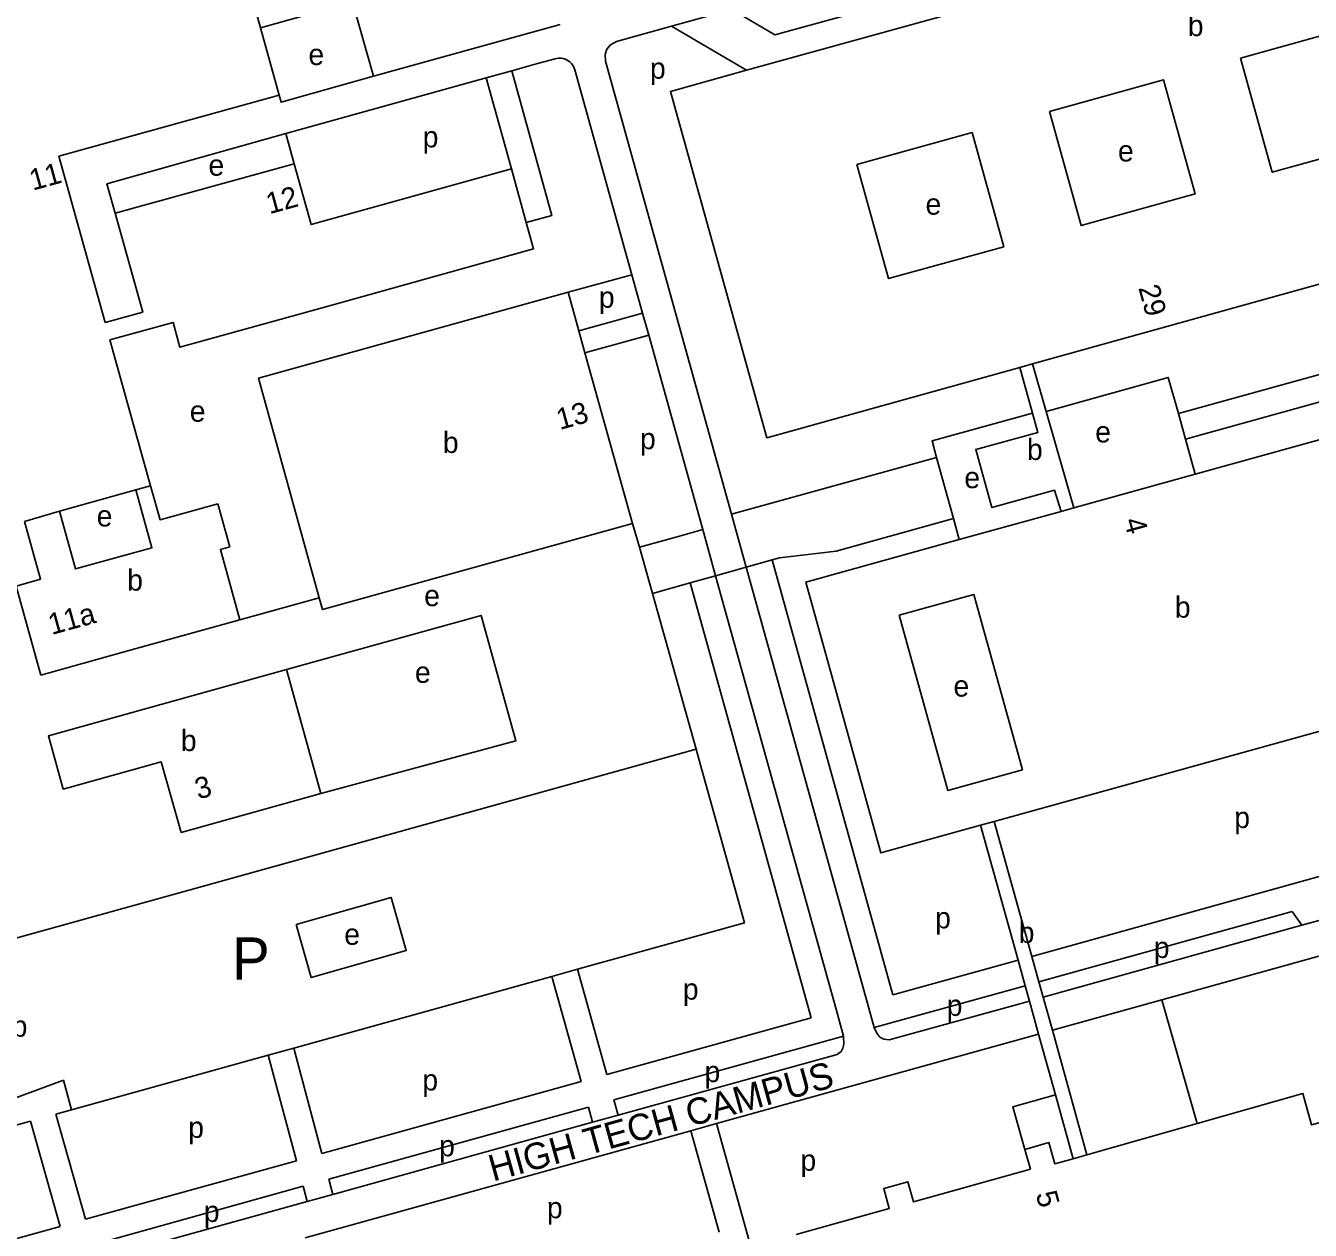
# Model space of a CAD drawing. Extents: x 158358 to 160383, y 379531 to 380764.
# Drawn here: x 159510.8 to 159753.6, y 380106.3 to 380334.2 of the extents above; entities that cross this region are included whole.
import ezdxf

# ---------------------------------------------------------------- set-up
doc = ezdxf.new("R2010")
doc.units = 0
for name, color, linetype in [('BLT_Basislijn', 7, 'Continuous'), ('BLT_Bebouwing', 7, 'Continuous'), ('BLT_Centroide', 7, 'Continuous'), ('BLT_Huisnummer', 7, 'Continuous'), ('BLT_Huisnummer_reeks', 7, 'Continuous'), ('BLT_Onderverdeling_panden', 7, 'Continuous'), ('BLT_Straatnaam', 7, 'Continuous'), ('BLT_Tekst_parkeren', 7, 'Continuous'), ('BLT_Vlakafsluiter', 7, 'Continuous')]:
    doc.layers.add(name, color=color, linetype=linetype)

msp = doc.modelspace()

# ---------------------------------------------------------------- linework, layer by layer
at = {"layer": 'BLT_Basislijn'}
for p, q in [((159647.01, 380325.72), (159632.85, 380334.04)), ((159602.59, 380307.08), (159597.81, 380324.29)), ((159613.28, 380283.77), (159625.32, 380287.07)), ((159627.35, 380279.77), (159625.32, 380287.07)), ((159615.3, 380276.47), (159627.35, 380279.77)), ((159628.51, 380275.61), (159627.35, 380279.77)), ((159616.46, 380272.31), (159628.51, 380275.61)), ((159638.72, 380238.86), (159628.51, 380275.61)), ((159682.93, 380252.51), (159686.12, 380240.96)), ((159626.8, 380235.51), (159625.42, 380240.04)), ((159638.72, 380238.86), (159633.91, 380237.51)), ((159633.91, 380237.51), (159626.8, 380235.51)), ((159636.34, 380228.77), (159629.24, 380226.78)), ((159641.15, 380230.12), (159636.34, 380228.77)), ((159566.23, 380225.94), (159551.25, 380221.82)), ((159700.92, 380158.15), (159776.17, 380179.06)), ((159702.26, 380153.33), (159750.14, 380166.64)), ((159750.14, 380166.64), (159751.98, 380164.03)), ((159620.59, 380135.81), (159615.03, 380155.71)), ((159674.68, 380150.85), (159698.32, 380157.42)), ((159615.77, 380134.47), (159610.21, 380154.37)), ((159671.13, 380144.67), (159699.65, 380152.6)), ((159664.01, 380147.89), (159665.35, 380143.07)), ((159671.13, 380144.67), (159669.79, 380149.49)), ((159725.52, 380149.93), (159732.18, 380126.53)), ((159566.75, 380120.85), (159561.41, 380140.81)), ((159561.93, 380119.51), (159556.59, 380139.48)), ((159622.74, 380128.11), (159621.93, 380131)), ((159617.92, 380126.77), (159617.11, 380129.66)), ((159517.25, 380107.09), (159511.64, 380126.98)), ((159522.06, 380108.43), (159516.45, 380128.32)), ((159641.3, 380126.52), (159647.79, 380103.2)), ((159636.48, 380125.18), (159641.83, 380105.97)), ((159563.99, 380111.78), (159563.22, 380114.68)), ((159568.81, 380113.12), (159568.04, 380116.02))]:
    msp.add_line(p, q, dxfattribs=at)
for points in [[(159644.21, 380337.2), (159652.38, 380332.4), (159681.59, 380340.51), (159679.69, 380347.06)], [(159555.14, 380333.77), (159572.55, 380338.64), (159576.49, 380324.6)], [(159632.85, 380334.04), (159644.21, 380337.2)], [(159576.49, 380324.6), (159611.78, 380334.41)], [(159644.14, 380241.8), (159620.33, 380327.45), (159620.27, 380328.69), (159620.61, 380329.72), (159621.29, 380330.54), (159622.42, 380331.14), (159632.85, 380334.04)], [(159625.32, 380287.07), (159614.55, 380325.84), (159614.3, 380326.45), (159613.96, 380326.96), (159613.6, 380327.33), (159613.13, 380327.65), (159612.6, 380327.88), (159611.99, 380328.02), (159611.42, 380328.03), (159610.85, 380327.92), (159607.51, 380326.99)], [(159602.62, 380325.63), (159597.81, 380324.29)], [(159607.51, 380326.99), (159602.62, 380325.63)], [(159605.38, 380296.91), (159610.23, 380298.25), (159602.62, 380325.63)], [(159576.49, 380324.6), (159559.03, 380319.7), (159558.67, 380320.99)], [(159597.81, 380324.29), (159559.9, 380313.75)], [(159559.9, 380313.75), (159526.11, 380304.26), (159527.67, 380298.69)], [(159559.9, 380313.75), (159561.48, 380308.06)], [(159813.81, 380248.2), (159804.49, 380281.82), (159728.62, 380260.79)], [(159809, 380246.85), (159801.01, 380275.67), (159729.96, 380255.97)], [(159703.64, 380261.22), (159726.71, 380267.65), (159728.62, 380260.79)], [(159701.07, 380260.89), (159682.06, 380255.64), (159682.93, 380252.51)], [(159728.62, 380260.79), (159729.96, 380255.97)], [(159729.96, 380255.97), (159731.8, 380249.35)], [(159682.93, 380252.51), (159644.14, 380241.8)], [(159646.93, 380231.74), (159644.14, 380241.8)], [(159686.12, 380240.96), (159663.96, 380234.8), (159653.25, 380233.53), (159651.84, 380233.13)], [(159687.22, 380236.97), (159686.12, 380240.96)], [(159641.15, 380230.12), (159638.72, 380238.86)], [(159629.24, 380226.78), (159626.8, 380235.51)], [(159651.84, 380233.13), (159646.93, 380231.74)], [(159674.68, 380150.85), (159651.84, 380233.13)], [(159669.79, 380149.49), (159646.93, 380231.74)], [(159659.2, 380146.55), (159636.34, 380228.77)], [(159664.01, 380147.89), (159641.15, 380230.12)], [(159637.46, 380197.33), (159629.24, 380226.78)], [(159560.05, 380212.38), (159596.84, 380222.62), (159603.43, 380198.94), (159566.54, 380188.95)], [(159751.98, 380164.03), (159757.09, 380165.46)], [(159703.07, 380150.44), (159751.98, 380164.03)], [(159725.52, 380149.93), (159755.15, 380158.17)], [(159671.13, 380144.67), (159671.61, 380143.63), (159672.21, 380142.88), (159672.96, 380142.48), (159673.96, 380142.35), (159700.46, 380149.71)], [(159704.81, 380144.17), (159725.52, 380149.93)], [(159620.59, 380135.81), (159659.2, 380146.55)], [(159621.93, 380131), (159665.35, 380143.07)], [(159622.74, 380128.11), (159664.15, 380139.62), (159664.87, 380140.17), (159665.23, 380140.78), (159665.42, 380141.57), (159665.35, 380143.07)], [(159641.3, 380126.52), (159702.19, 380143.45)], [(159566.75, 380120.85), (159615.77, 380134.47)], [(159699.59, 380121.62), (159697.33, 380129.72), (159705.38, 380131.95)], [(159568.04, 380116.02), (159617.11, 380129.66)], [(159479.08, 380112.67), (159489.18, 380115.63), (159493.51, 380118.12), (159498.87, 380123.44), (159511.64, 380126.98)], [(159568.81, 380113.12), (159617.92, 380126.77)], [(159617.92, 380126.77), (159622.74, 380128.11)], [(159636.48, 380125.18), (159641.3, 380126.52)], [(159563.57, 380104.92), (159636.48, 380125.18)], [(159522.06, 380108.43), (159561.93, 380119.51)], [(159523.42, 380103.62), (159563.22, 380114.68)], [(159524.24, 380100.73), (159563.99, 380111.78)], [(159563.99, 380111.78), (159568.81, 380113.12)], [(159483.15, 380097.61), (159517.25, 380107.09)]]:
    msp.add_lwpolyline(points, dxfattribs=at)
at = {"layer": 'BLT_Bebouwing'}
for p, q in [((159616.46, 380272.31), (159615.3, 380276.47)), ((159623.05, 380248.56), (159616.46, 380272.31)), ((159703.64, 380261.22), (159701.07, 380270.2)), ((159708.87, 380242.99), (159703.64, 380261.22)), ((159625.42, 380240.04), (159623.05, 380248.56)), ((159549.35, 380235.62), (159547.08, 380243.76)), ((159691.23, 380182.95), (159698.32, 380157.42)), ((159700.92, 380158.15), (159693.83, 380183.67)), ((159702.26, 380153.33), (159700.92, 380158.15)), ((159698.32, 380157.42), (159699.65, 380152.6)), ((159703.07, 380150.44), (159702.26, 380153.33)), ((159699.65, 380152.6), (159700.46, 380149.71)), ((159704.81, 380144.17), (159703.07, 380150.44)), ((159700.46, 380149.71), (159702.19, 380143.45)), ((159702.19, 380143.45), (159705.38, 380131.95)), ((159711.35, 380120.64), (159704.81, 380144.17)), ((159519.42, 380129.15), (159556.59, 380139.48)), ((159493.53, 380125.73), (159517.88, 380134.74)), ((159519.42, 380129.15), (159517.88, 380134.74)), ((159705.38, 380131.95), (159708.73, 380119.89)), ((159519.42, 380129.15), (159516.45, 380128.32))]:
    msp.add_line(p, q, dxfattribs=at)
for points in [[(159474.11, 380354.2), (159493.76, 380359.64), (159491.98, 380366.07), (159542.36, 380380.02), (159555.14, 380333.77)], [(159647.01, 380325.72), (159705.25, 380341.89), (159703.43, 380348.44), (159718.13, 380352.52), (159719.95, 380345.97), (159770.83, 380360.09)], [(159775.8, 380342.21), (159789.03, 380294.66), (159701.07, 380270.2)], [(159555.14, 380333.77), (159558.67, 380320.99)], [(159740.39, 380328.03), (159746.38, 380306.45), (159768.09, 380312.47), (159762.1, 380334.06), (159740.39, 380328.03)], [(159650.83, 380256.23), (159632.61, 380321.72), (159647.01, 380325.72)], [(159704.27, 380317.95), (159710.27, 380296.36), (159731.8, 380302.34), (159725.81, 380323.93), (159704.27, 380317.95)], [(159525.78, 380278), (159517.04, 380309.46), (159558.67, 380320.99)], [(159667.86, 380307.91), (159673.85, 380286.32), (159695.62, 380292.36), (159689.63, 380313.95), (159667.86, 380307.91)], [(159561.48, 380308.06), (159527.67, 380298.69)], [(159602.59, 380307.08), (159564.69, 380296.53), (159561.48, 380308.06)], [(159605.38, 380296.91), (159602.59, 380307.08)], [(159527.67, 380298.69), (159532.87, 380279.97), (159525.78, 380278)], [(159568.6, 380281.32), (159606.75, 380291.94), (159605.38, 380296.91)], [(159613.28, 380283.77), (159554.78, 380267.47), (159566.23, 380225.94)], [(159615.3, 380276.47), (159613.28, 380283.77)], [(159526.69, 380274.73), (159538.62, 380278.04), (159539.92, 380273.35), (159568.6, 380281.32)], [(159534.36, 380247.14), (159526.69, 380274.73)], [(159698.68, 380269.54), (159650.83, 380256.23)], [(159698.68, 380269.54), (159701.07, 380260.89)], [(159731.8, 380249.35), (159796.63, 380267.34)], [(159701.07, 380260.89), (159702.08, 380257.23), (159690.34, 380253.99), (159693.37, 380243.04), (159705.19, 380246.31), (159706.46, 380242.31)], [(159708.87, 380242.99), (159731.8, 380249.35)], [(159531.58, 380246.36), (159534.61, 380235.42), (159520.2, 380231.43), (159517.17, 380242.37)], [(159517.17, 380242.37), (159531.58, 380246.36)], [(159547.08, 380243.76), (159536.15, 380240.72), (159534.36, 380247.14)], [(159510.53, 380240.41), (159513.59, 380229.46), (159508.97, 380228.17), (159513.62, 380211.36)], [(159566.23, 380225.94), (159566.84, 380223.73), (159625.42, 380240.04)], [(159687.22, 380236.97), (159706.46, 380242.31)], [(159551.25, 380221.82), (159547.55, 380235.12), (159549.35, 380235.62)], [(159691.23, 380182.95), (159672.37, 380177.72), (159658.19, 380228.92), (159687.22, 380236.97)], [(159675.86, 380222.7), (159689.97, 380226.61), (159699.15, 380193.43), (159685.04, 380189.52), (159675.86, 380222.7)], [(159530.5, 380216.05), (159551.25, 380221.82)], [(159513.62, 380211.36), (159530.5, 380216.05)], [(159560.05, 380212.38), (159533.59, 380205.01)], [(159566.54, 380188.95), (159560.05, 380212.38)], [(159784.5, 380208.82), (159693.83, 380183.67)], [(159533.59, 380205.01), (159515.05, 380199.84), (159517.86, 380189.79), (159536.38, 380194.94), (159540.13, 380181.59)], [(159542.98, 380171.08), (159637.46, 380197.33)], [(159638.23, 380194.59), (159637.46, 380197.33)], [(159615.03, 380155.71), (159646.6, 380164.48), (159638.23, 380194.59)], [(159540.13, 380181.59), (159566.54, 380188.95)], [(159482.93, 380154.39), (159542.98, 380171.08)], [(159610.21, 380154.37), (159615.03, 380155.71)], [(159561.41, 380140.81), (159610.21, 380154.37)], [(159556.59, 380139.48), (159561.41, 380140.81)], [(159732.18, 380126.53), (159752.18, 380132.19), (159753.81, 380126.29), (159763.63, 380129.02), (159768.01, 380113.16), (159762.28, 380111.58), (159764.96, 380101.97)], [(159711.35, 380120.64), (159732.18, 380126.53)], [(159656.41, 380105.57), (159673.99, 380110.47), (159672.94, 380114.23), (159677.52, 380115.51), (159678.56, 380111.75), (159700.65, 380117.89), (159699.59, 380121.62)], [(159699.59, 380121.62), (159704.17, 380122.92), (159705.3, 380118.92)], [(159705.3, 380118.92), (159708.73, 380119.89)]]:
    msp.add_lwpolyline(points, dxfattribs=at)
msp.add_lwpolyline([(159561.86, 380164.17), (159564.73, 380154.14), (159582.7, 380159.28), (159579.83, 380169.31)], close=True, dxfattribs=at)
at = {"layer": 'BLT_Onderverdeling_panden'}
for p, q in [((159698.68, 380269.54), (159701.07, 380270.2)), ((159531.58, 380246.36), (159534.36, 380247.14)), ((159706.46, 380242.31), (159708.87, 380242.99)), ((159517.17, 380242.37), (159510.53, 380240.41)), ((159691.23, 380182.95), (159693.83, 380183.67)), ((159708.73, 380119.89), (159711.35, 380120.64))]:
    msp.add_line(p, q, dxfattribs=at)
at = {"layer": 'BLT_Vlakafsluiter'}
msp.add_line((159641.15, 380230.12), (159646.93, 380231.74), dxfattribs=at)

# ---------------------------------------------------------------- texts
at = {"layer": 'BLT_Centroide'}
for s, p in [('b', (159730.41, 380332.18)), ('e', (159564.2, 380326.72)), ('p', (159628.75, 380324.12)), ('p', (159585.8, 380311.14)), ('e', (159717.21, 380308.48)), ('e', (159545.31, 380305.79)), ('e', (159680.84, 380298.42)), ('p', (159619.1, 380280.82)), ('e', (159541.77, 380259.26)), ('b', (159589.61, 380253.35)), ('p', (159626.87, 380254.06)), ('e', (159712.91, 380255.35)), ('b', (159700.01, 380252.03)), ('e', (159688.17, 380246.69)), ('e', (159524.18, 380239.45)), ('b', (159529.95, 380227.32)), ('e', (159586.08, 380224.38)), ('b', (159727.96, 380222.2)), ('e', (159584.33, 380209.88)), ('e', (159686.12, 380207.28)), ('b', (159540.09, 380196.97)), ('p', (159739.19, 380182.42)), ('p', (159682.65, 380163.45)), ('b', (159698.45, 380160.68)), ('e', (159570.97, 380160.33)), ('p', (159723.98, 380157.84)), ('p', (159634.97, 380149.97)), ('p', (159684.84, 380146.89)), ('b', (159508.11, 380142.95)), ('p', (159585.73, 380132.79)), ('p', (159639.07, 380134.36)), ('p', (159541.48, 380123.82)), ('p', (159588.9, 380120.34)), ('p', (159657.2, 380117.61)), ('p', (159609.28, 380108.62)), ('p', (159544.43, 380107.92))]:
    msp.add_text(s, height=4, dxfattribs=at).set_placement(p)
at = {"layer": 'BLT_Huisnummer'}
for s, rotation, p in [('13', 15.4676, (159611.71, 380257.69)), ('11a', 15.4676, (159515.67, 380218.92)), ('3', 15.5208, (159543.37, 380187.8)), ('5', 285.3861, (159701.64, 380113.21))]:
    msp.add_text(s, height=4, rotation=rotation, dxfattribs=at).set_placement(p)
at = {"layer": 'BLT_Huisnummer_reeks'}
for s, rotation, p in [('11', 15.4676, (159512.1, 380302.95)), ('12', 15.4676, (159556.83, 380298.49)), ('29', 285.5471, (159721.03, 380284.59)), ('4', 285.4802, (159718.29, 380240.57))]:
    msp.add_text(s, height=4, rotation=rotation, dxfattribs=at).set_placement(p)
at = {"layer": 'BLT_Straatnaam'}
msp.add_text('HIGH TECH CAMPUS', height=5, rotation=15.534, dxfattribs=at).set_placement((159599.08, 380115.54))
at = {"layer": 'BLT_Tekst_parkeren'}
msp.add_text('P', height=8, dxfattribs=at).set_placement((159549.75, 380153.73))

doc.saveas('drawing.dxf')
